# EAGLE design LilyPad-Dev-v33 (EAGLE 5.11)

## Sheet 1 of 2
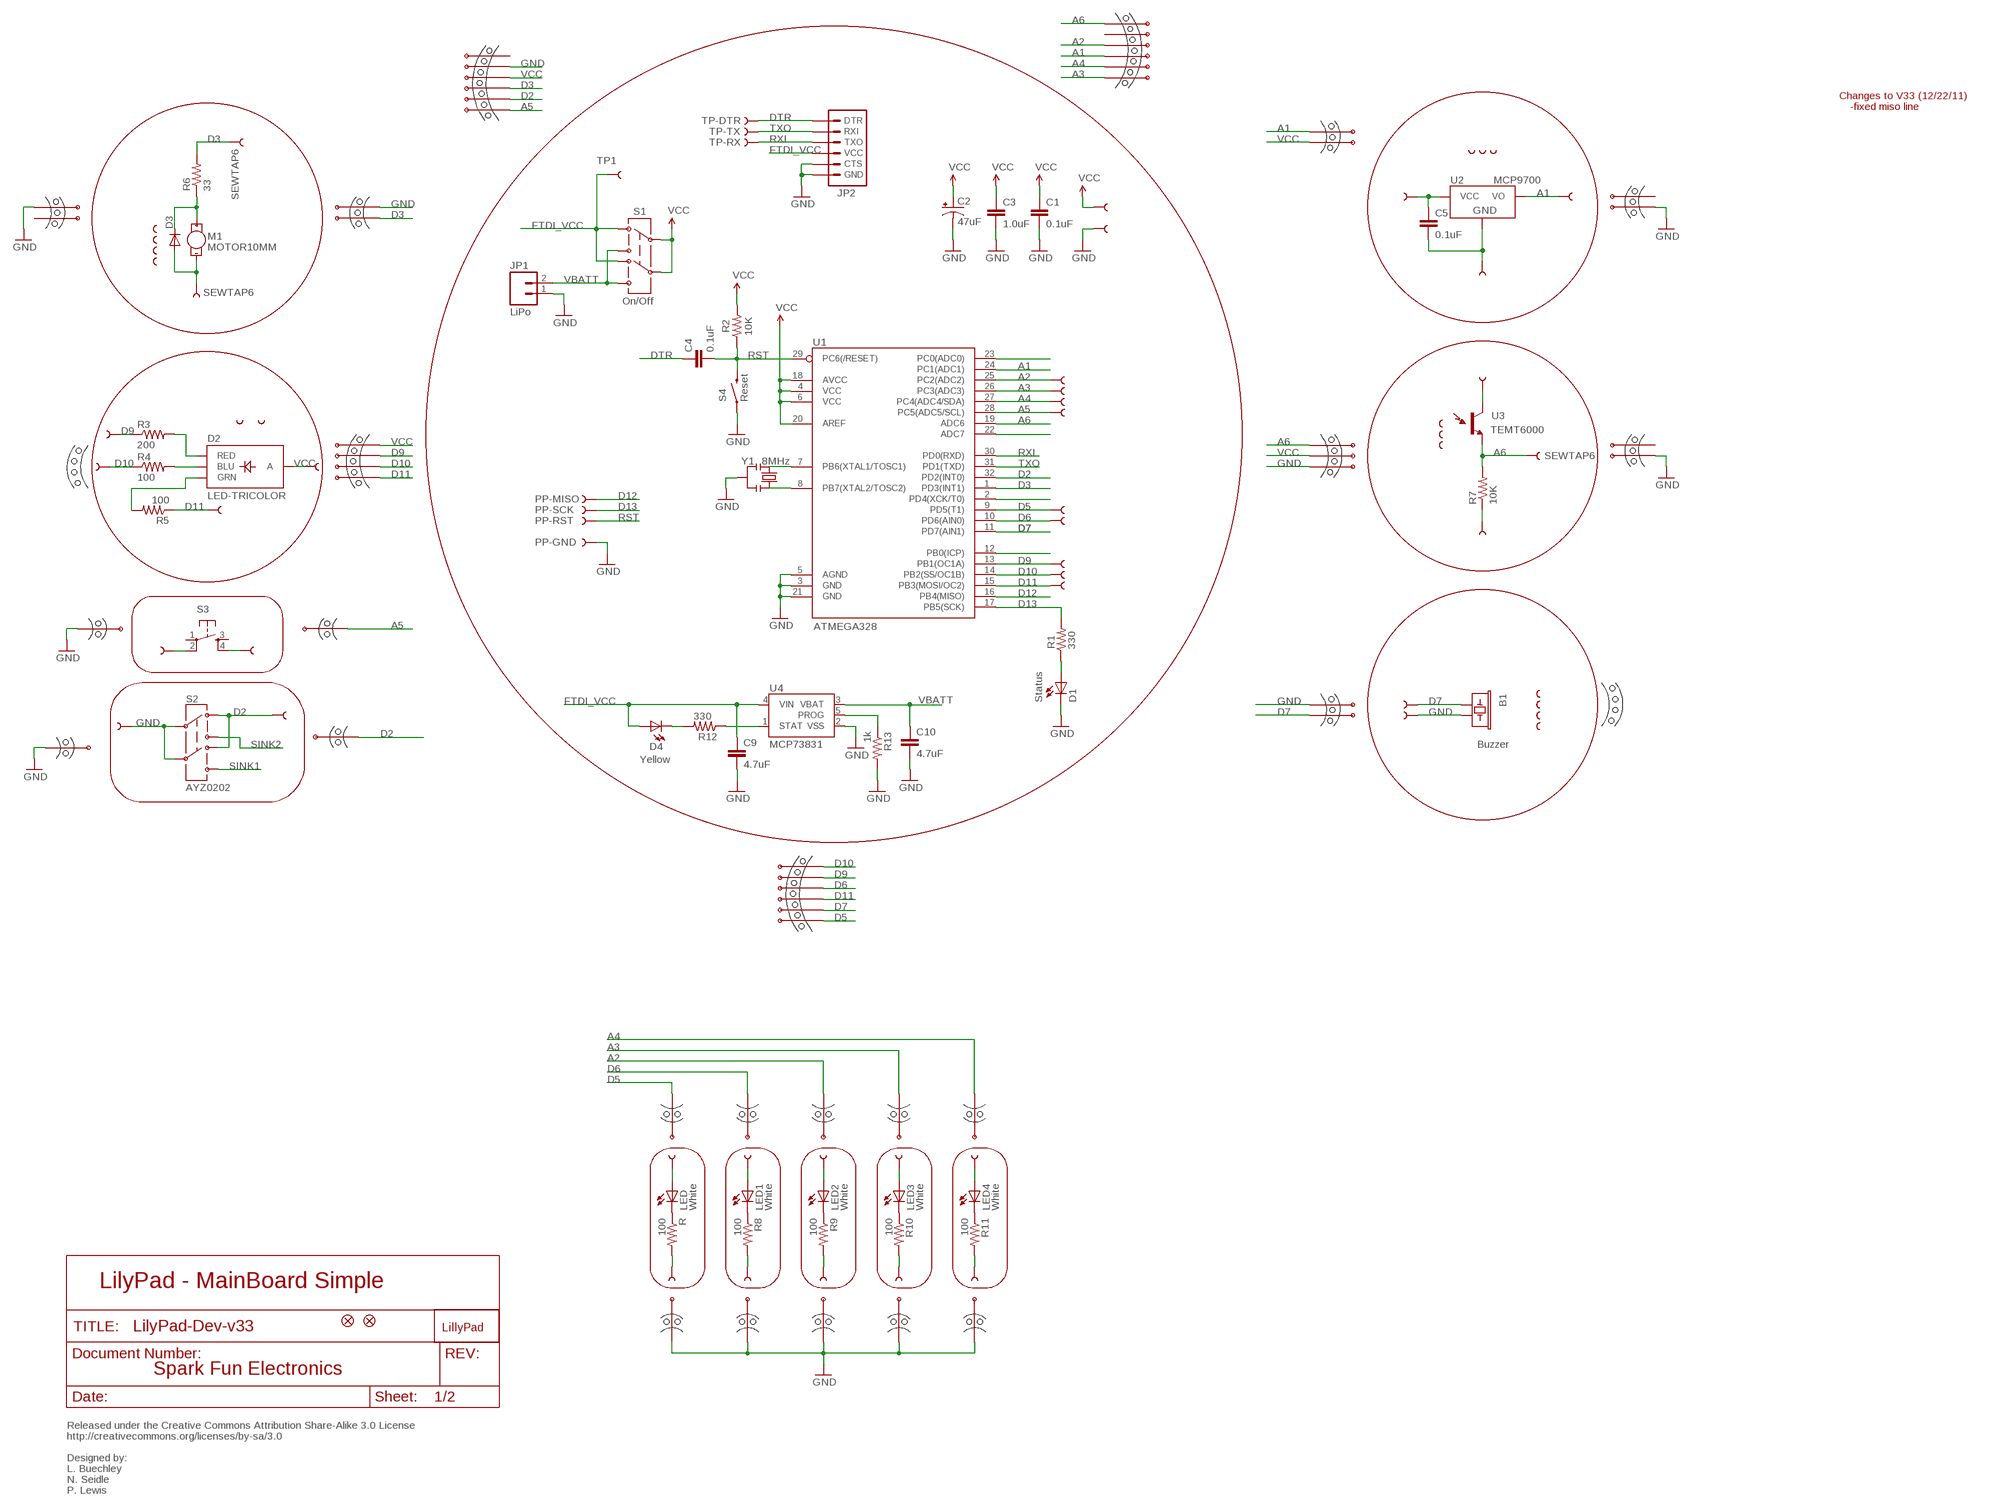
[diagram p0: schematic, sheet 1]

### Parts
1  SEWTAP-NOHOLE2  [PETAL-NOHOLE-2SIDE]
2  SEWTAP-NOHOLE2  [PETAL-NOHOLE-2SIDE]
3  SEWTAP-NOHOLE2  [PETAL-NOHOLE-2SIDE]
4  SEWTAP-NOHOLE2  [PETAL-NOHOLE-2SIDE]
A2/16  SEWTAP9  [PETAL-LONG-1-2SIDE]
A3/17  SEWTAP9  [PETAL-LONG-1-2SIDE]
A4/18  SEWTAP9  [PETAL-LONG-1-2SIDE]
A5/19  SEWTAP9  [PETAL-LONG-1-2SIDE]
B1  Buzzer  BUZZERSMD2  [BUZZER-CCV]
BUTTON-  SEWTAP8  SEWTAP4  [PETAL-SMALL]
BUTTONS  SEWTAP8  SEWTAP4  [PETAL-SMALL]
C1  0.1uF  CAP0402-CAP  [0402-CAP]
C2  47uF  CAP_POL3528  [EIA3528]
C3  1.0uF  CAP0402-CAP  [0402-CAP]
C4  0.1uF  CAP0402-CAP  [0402-CAP]
C5  0.1uF  CAP0603-CAP  [0603-CAP]
C9  4.7uF  CAP0402-CAP  [0402-CAP]
C10  4.7uF  CAP0402-CAP  [0402-CAP]
D1  Status  LED0603  [LED-0603]
D2  LED-TRICOLOR  [LED-TRICOLOR-SMD]
D3  DIODESOD  [SOD-323]
D4  Yellow  LED0603  [LED-0603]
JP1  LiPo  M02-JST-2MM-SMT  [JST-2-SMD]
JP2  ARDUINO_SERIAL_PROGRAMSMD  [1X06-SMD]
JP3  FIDUCIAL1X2  [FIDUCIAL-1X2]
JP4  FIDUCIAL1X2  [FIDUCIAL-1X2]
LED  White  LED1206  [LED-1206]
LED1  White  LED1206  [LED-1206]
LED2  White  LED1206  [LED-1206]
LED3  White  LED1206  [LED-1206]
LED4  White  LED1206  [LED-1206]
LED+  SEWTAP6  [PETAL-SMALL-2SIDE]
LED+1  SEWTAP6  [PETAL-SMALL-2SIDE]
LED+2  SEWTAP6  [PETAL-SMALL-2SIDE]
LED+3  SEWTAP6  [PETAL-SMALL-2SIDE]
LED+4  SEWTAP6  [PETAL-SMALL-2SIDE]
LED-  SEWTAP6  [PETAL-SMALL-2SIDE]
LED-1  SEWTAP6  [PETAL-SMALL-2SIDE]
LED-2  SEWTAP6  [PETAL-SMALL-2SIDE]
LED-3  SEWTAP6  [PETAL-SMALL-2SIDE]
LED-4  SEWTAP6  [PETAL-SMALL-2SIDE]
LIGHT1  SEWTAP-NOHOLE2  [PETAL-NOHOLE-2SIDE]
LIGHT2  SEWTAP-NOHOLE2  [PETAL-NOHOLE-2SIDE]
LIGHT3  SEWTAP-NOHOLE2  [PETAL-NOHOLE-2SIDE]
LIGHT+  SEWTAP6  SEWTAP4  [PETAL-SMALL]
LIGHT-  SEWTAP6  SEWTAP4  [PETAL-SMALL]
LIGHTS  SEWTAP6  SEWTAP4  [PETAL-SMALL]
LOGO  LOGO-LPLPA  [LOGO-LPA]
M1  MOTOR10MM  [VIBE-MOTOR-10MM]
PP-GND  TEST-POINT3X5  [PAD.03X.05]
PP-MISO  TEST-POINT3X5  [PAD.03X.05]
PP-RST  TEST-POINT3X5  [PAD.03X.05]
PP-SCK  TEST-POINT3X5  [PAD.03X.05]
R  100  RESISTOR0603-RES  [0603-RES]
R1  330  RESISTOR0402-RES  [0402-RES]
R2  10K  RESISTOR0402-RES  [0402-RES]
R3  200  RESISTOR0402-RES  [0402-RES]
R4  100  RESISTOR0402-RES  [0402-RES]
R5  100  RESISTOR0402-RES  [0402-RES]
R6  33  RESISTOR0402-RES  [0402-RES]
R7  10K  RESISTOR0402-RES  [0402-RES]
R8  100  RESISTOR0603-RES  [0603-RES]
R9  100  RESISTOR0603-RES  [0603-RES]
R10  100  RESISTOR0603-RES  [0603-RES]
R11  100  RESISTOR0603-RES  [0603-RES]
R12  330  RESISTOR0402-RES  [0402-RES]
R13  1k  RESISTOR0402-RES  [0402-RES]
S1  On/Off  AYZ0202  [AYZ0202]
S2  AYZ0202  [AYZ0202]
S3  TAC_SWITCHSMD  [TACTILE_SWITCH_SMD]
S4  Reset  SWITCH-MOMENTARY-2SMD  [TACTILE_SWITCH_SMD]
SLIDEOFF  SEWTAP8  SEWTAP4  [PETAL-SMALL]
SLIDEON  SEWTAP8  SEWTAP4  [PETAL-SMALL]
TEMP1  SEWTAP-NOHOLE2  [PETAL-NOHOLE-2SIDE]
TEMP2  SEWTAP-NOHOLE2  [PETAL-NOHOLE-2SIDE]
TEMP3  SEWTAP-NOHOLE2  [PETAL-NOHOLE-2SIDE]
TEMP+  SEWTAP6  SEWTAP4  [PETAL-SMALL]
TEMP-  SEWTAP6  SEWTAP4  [PETAL-SMALL]
TEMPS  SEWTAP6  SEWTAP4  [PETAL-SMALL]
TP1  TEST-POINT3X5  [PAD.03X.05]
TP-DTR  TEST-POINT3X5  [PAD.03X.05]
TP-RX  TEST-POINT3X5  [PAD.03X.05]
TP-TX  TEST-POINT3X5  [PAD.03X.05]
U1  ATMEGA328  ATMEGA168  [TQFP32-08]
U2  MCP9700  MCP9700SMD  [SOT23-3]
U3  TEMT6000  [TEMT6000-SEN]
U4  MCP73831  [SOT23-5]
U$1  SEWTAP9  [PETAL-LONG-1-2SIDE]
U$2  MOUSE-BITE-2  [MOUSE-BITE-2]
U$3  MOUSE-BITE-2  [MOUSE-BITE-2]
U$4  SEWTAP9  [PETAL-LONG-1-2SIDE]
U$5  MOUSE-BITE-2  [MOUSE-BITE-2]
U$6  MOUSE-BITE-2  [MOUSE-BITE-2]
U$7  MOUSE-BITE-66  [MOUSE-BITE-6]
U$8  MOUSE-BITE-66  [MOUSE-BITE-6]
U$10  MOUSE-BITE-12_HOLES  [MOUST-BITE-1-(2_HOLES)]
U$11  MOUSE-BITE-12_HOLES  [MOUST-BITE-1-(2_HOLES)]
U$12  MOUSE-BITE-12_HOLES  [MOUST-BITE-1-(2_HOLES)]
U$13  MOUSE-BITE-12_HOLES  [MOUST-BITE-1-(2_HOLES)]
U$14  MOUSE-BITE-12_HOLES  [MOUST-BITE-1-(2_HOLES)]
U$15  MOUSE-BITE-12_HOLES  [MOUST-BITE-1-(2_HOLES)]
U$16  MOUSE-BITE-12_HOLES  [MOUST-BITE-1-(2_HOLES)]
U$17  MOUSE-BITE-12_HOLES  [MOUST-BITE-1-(2_HOLES)]
U$18  MOUSE-BITE-12_HOLES  [MOUST-BITE-1-(2_HOLES)]
U$19  MOUSE-BITE-12_HOLES  [MOUST-BITE-1-(2_HOLES)]
U$20  MOUSE-BITE-4  [MOUSE-BITE-4]
U$22  SEWTAP6  [PETAL-SMALL-2SIDE]
U$23  SEWTAP6  [PETAL-SMALL-2SIDE]
U$24  SEWTAP6  [PETAL-SMALL-2SIDE]
U$25  SEWTAP6  [PETAL-SMALL-2SIDE]
U$26  SEWTAP-NOHOLE2  [PETAL-NOHOLE-2SIDE]
U$27  SEWTAP-NOHOLE2  [PETAL-NOHOLE-2SIDE]
U$32  MOUSE-BITE-2  [MOUSE-BITE-2]
U$32-  SEWTAP6  SEWTAP4  [PETAL-SMALL]
U$33  MOUSE-BITE-3  [MOUSE-BITE-3]
U$33+  SEWTAP6  SEWTAP4  [PETAL-SMALL]
U$37  SEWTAP9  [PETAL-LONG-1-2SIDE]
U$39  SEWTAP9  [PETAL-LONG-1-2SIDE]
U$40  MOUSE-BITE-1  [MOUSE-BITE-1]
U$41  SEWTAP9  [PETAL-LONG-1-2SIDE]
U$42  MOUSE-BITE-1  [MOUSE-BITE-1]
U$43  SEWTAP9  [PETAL-LONG-1-2SIDE]
U$44  MOUSE-BITE-1  [MOUSE-BITE-1]
U$45  SEWTAP9  [PETAL-LONG-1-2SIDE]
U$46  MOUSE-BITE-1  [MOUSE-BITE-1]
U$47  MOUSE-BITE-2  [MOUSE-BITE-2]
U$48  MOUSE-BITE-3(NO_PADS)  [MOUSE-BITE-3(NO_PADS)]
U$49  MOUSE-BITE-3(NO_PADS)  [MOUSE-BITE-3(NO_PADS)]
U$51  MOUSE-BITE-66  [MOUSE-BITE-6]
VIBE1  SEWTAP-NOHOLE2  [PETAL-NOHOLE-2SIDE]
VIBE2  SEWTAP-NOHOLE2  [PETAL-NOHOLE-2SIDE]
VIBE3  SEWTAP-NOHOLE2  [PETAL-NOHOLE-2SIDE]
VIBE4  SEWTAP-NOHOLE2  [PETAL-NOHOLE-2SIDE]
VIBE+  SEWTAP6  SEWTAP4  [PETAL-SMALL]
VIBE-  SEWTAP6  SEWTAP4  [PETAL-SMALL]
Y1  8MHz  RESONATORSMD  [RESONATOR-SMD]

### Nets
A1: TEMPS.1 U1.24(PC1(ADC1)) U2.2(VO) U$2.P$1 U$7.P$4
A2: A2/16.1 U1.25(PC2(ADC2)) U$7.P$3 U$12.P$1
A3: A3/17.1 U1.26(PC3(ADC3)) U$7.P$6 U$13.P$1
A4: A4/18.1 U1.27(PC4(ADC4/SDA)) U$7.P$5 U$14.P$1
A5: A5/19.1 BUTTONS.1 S3.2 U1.28(PC5(ADC5/SCL)) U$8.P$1 U$40.P$1
A6: LIGHTS.1 R7.2 U1.19(ADC6) U3.EMITTER(E1) U$7.P$1 U$33.P$1
BLU: D2.B(BLU) R4.2
D2: S2.3 S2.6 SLIDEON.1 U1.32(PD2(INT0)) U$8.P$2 U$46.P$1
D3: R6.2 U1.1(PD3(INT1)) U$5.P$1 U$8.P$3 VIBE+.1
D5: U1.9(PD5(T1)) U$10.P$1 U$41.1 U$51.P$1
D6: U1.10(PD6(AIN0)) U$1.1 U$11.P$1 U$51.P$4
D7: B1.+ U1.11(PD7(AIN1)) U$32.P$2 U$33+.1 U$51.P$2
D9: R3.1 U1.13(PB1(OC1A)) U$20.P$3 U$22.1 U$37.1 U$51.P$5
D10: R4.1 U1.14(PB2(SS/OC1B)) U$20.P$2 U$24.1 U$39.1 U$51.P$6
D11: R5.1 U1.15(PB3(MOSI/OC2)) U$4.1 U$20.P$1 U$23.1 U$51.P$3
D12: PP-MISO.P$1 U1.16(PB4(MISO))
D13: PP-SCK.P$1 R1.2 U1.17(PB5(SCK))
DTR: C4.1 JP2.1(DTR) TP-DTR.P$1
FTDI_VCC: C9.1 D4.A JP2.4(VCC) S1.3 S1.6 TP1.P$1 U4.4(VIN)
GND [VCC]: B1.- BUTTON-.1 C1.2 C2.C(-) C3.2 C5.2 C9.2 C10.2 D1.C D3.2(A) JP1.1 JP2.5(CTS) JP2.6(GND) LIGHT-.1 M1.- PP-GND.P$1 R7.1 R13.2 S2.2 S2.5 S3.4 S4.1 SLIDEOFF.1 TEMP-.1 U1.3(GND) U1.5(AGND) U1.21(GND) U2.3(GND) U4.2(VSS) U$3.P$1 U$5.P$2 U$6.P$1 U$8.P$5 U$15.P$1 U$16.P$1 U$17.P$1 U$18.P$1 U$19.P$1 U$32-.1 U$32.P$1 U$33.P$3 U$42.P$1 U$43.1 U$44.P$1 U$47.P$1 VIBE-.1 Y1.2
GRN: D2.G(GRN) R5.2
N$1: U1.7(PB6(XTAL1/TOSC1)) Y1.1
N$2: D1.A R1.1
N$3: U1.8(PB7(XTAL2/TOSC2)) Y1.3
N$5: U1.23(PC0(ADC0))
N$8: U1.22(ADC7)
N$10: D3.1(C) M1.+ R6.1
N$12: U1.2(PD4(XCK/T0))
N$14: U1.12(PB0(ICP))
N$18: LED.C R.1
N$19: LED+.1 LED.A
N$20: LED-.1 R.2
N$21: LED1.C R8.1
N$22: LED1.A LED+1.1
N$23: LED-1.1 R8.2
N$24: LED2.C R9.1
N$25: LED2.A LED+2.1
N$26: LED-2.1 R9.2
N$27: LED3.C R10.1
N$28: LED3.A LED+3.1
N$29: LED-3.1 R10.2
N$30: LED4.C R11.1
N$31: LED4.A LED+4.1
N$32: LED-4.1 R11.2
N$33: D4.C R12.2
PROG: R13.1 U4.5(PROG)
RED: D2.R(RED) R3.2
RST: C4.2 PP-RST.P$1 R2.1 S4.3 U1.29(PC6(/RESET))
RXI: JP2.3(TXO) TP-RX.P$1 U1.30(PD0(RXD))
SINK1: S2.4
SINK2: S2.1
STAT: R12.1 U4.1(STAT)
TXO: JP2.2(RXI) TP-TX.P$1 U1.31(PD1(TXD))
VBATT: C10.1 JP1.2 S1.1 S1.4 U4.3(VBAT)
VCC [VCC]: C1.1 C2.A(+) C3.1 C5.1 D2.A LIGHT+.1 R2.2 S1.2 S1.5 TEMP+.1 U1.4(VCC) U1.6(VCC) U1.18(AVCC) U1.20(AREF) U2.1(VCC) U3.COLLECTOR(C1) U$2.P$2 U$8.P$4 U$20.P$4 U$25.1 U$33.P$2 U$45.1
Unconnected: S3.1 S3.3 U$3.P$2 U$6.P$2 U$7.P$2 U$8.P$6 U$47.P$2

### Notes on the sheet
- Changes to V33 (12/22/11)
- -fixed miso line
- LilyPad - MainBoard Simple
- Spark Fun Electronics
- Released under the Creative Commons Attribution Share-Alike 3.0 License
- http://creativecommons.org/licenses/by-sa/3.0
- Designed by:
- L. Buechley
- N. Seidle
- P. Lewis

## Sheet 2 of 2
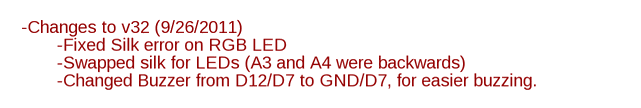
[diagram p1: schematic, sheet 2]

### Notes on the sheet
- -Changes to v32 (9/26/2011)
- -Fixed Silk error on RGB LED
- -Swapped silk for LEDs (A3 and A4 were backwards)
- -Changed Buzzer from D12/D7 to GND/D7, for easier buzzing.

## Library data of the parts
1-4 LIGHT1-LIGHT3 TEMP1-TEMP3 U$26 U$27 VIBE1-VIBE4 = LilyPad-Wearables:SEWTAP-NOHOLE
A2/16 A3/17 A4/18 A5/19 BUTTON- BUTTONS LED+ LED+1-LED+4 LED- LED-1-LED-4 LIGHT+ LIGHT- LIGHTS SLIDEOFF SLIDEON TEMP+ TEMP- TEMPS U$1 U$4 U$22-U$25 U$32- U$33+ U$37 U$39 U$41 U$43 U$45 VIBE+ VIBE- = LilyPad-Wearables:SEWTAP
B1 = SparkFun:BUZZER: Buzzer 12mm
C1 C3-C5 C9 C10 = SparkFun:CAP: Capacitor
C2 = SparkFun:CAP_POL: Capacitor Polarized
D1 D4 = SparkFun:LED: LEDs
D2 = SparkFun:LED-TRICOLOR: Tri-Color LED SMD Proven layout and schematic for triple color LED in SMD package - common anode. Spark Fun Electronics SKU : COM-07844
D3 = SparkFun:DIODE: Diode
JP1 = SparkFun:M02: Header 2
JP2 = SparkFun:ARDUINO_SERIAL_PROGRAM
JP3 JP4 = SparkFun:FIDUCIAL: Fiducial Alignment Points
LED LED1-LED4 = SparkFun-3-2-07:LED: LEDs
LOGO = LilyPad-Wearables:LOGO-LP
M1 = SparkFun:MOTOR: Vibration Motor
PP-GND PP-MISO PP-RST PP-SCK TP1 TP-DTR TP-RX TP-TX = SparkFun:TEST-POINT
R R1-R13 = SparkFun:RESISTOR: Resistor
S1 S2 = SparkFun:AYZ0202: SPDT Slide Switch Simple SMD single-pull double-throw slide switch. Good for less than 350mA power switch, switching UARTs between devices, etc. Spark Fun Electronics SKU : COM-00597
S3 = SparkFun:TAC_SWITCH: Momentary Switch Button commonly used for reset or general input. Spark Fun Electronics SKU : COM-00097
S4 = SparkFun:SWITCH-MOMENTARY-2
U1 = SparkFun:ATMEGA168
U2 = SparkFun:MCP9700
U3 = SparkFun:TEMT6000: Ambient Light Sensor
U4 = SparkFun:MCP73831: Microchip's MCP73831 Miniature single cell, fully integrated Li-Ion, Li-polymer charge management controller http://ww1.microchip.com/downloads/en/DeviceDoc/21984a.pdf
U$2 U$3 U$5 U$6 U$32 U$47 = Testing:MOUSE-BITE-2
U$7 U$8 U$51 = Testing:MOUSE-BITE-6
U$10-U$19 U$40 U$42 U$44 U$46 = Testing:MOUSE-BITE-1
U$20 = Testing:MOUSE-BITE-4
U$33 = Testing:MOUSE-BITE-3
U$48 U$49 = Testing:MOUSE-BITE-3(NO_PADS)
Y1 = SparkFun:RESONATOR: Resonator Small SMD resonator. This is the itty bitty 10/20MHz resonators with built in caps. CSTCE10M0G55 and CSTCE20M0V53. Footprint has been reviewed closely but hasn't been tested yet.

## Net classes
1 VCC: width 0.203 mm

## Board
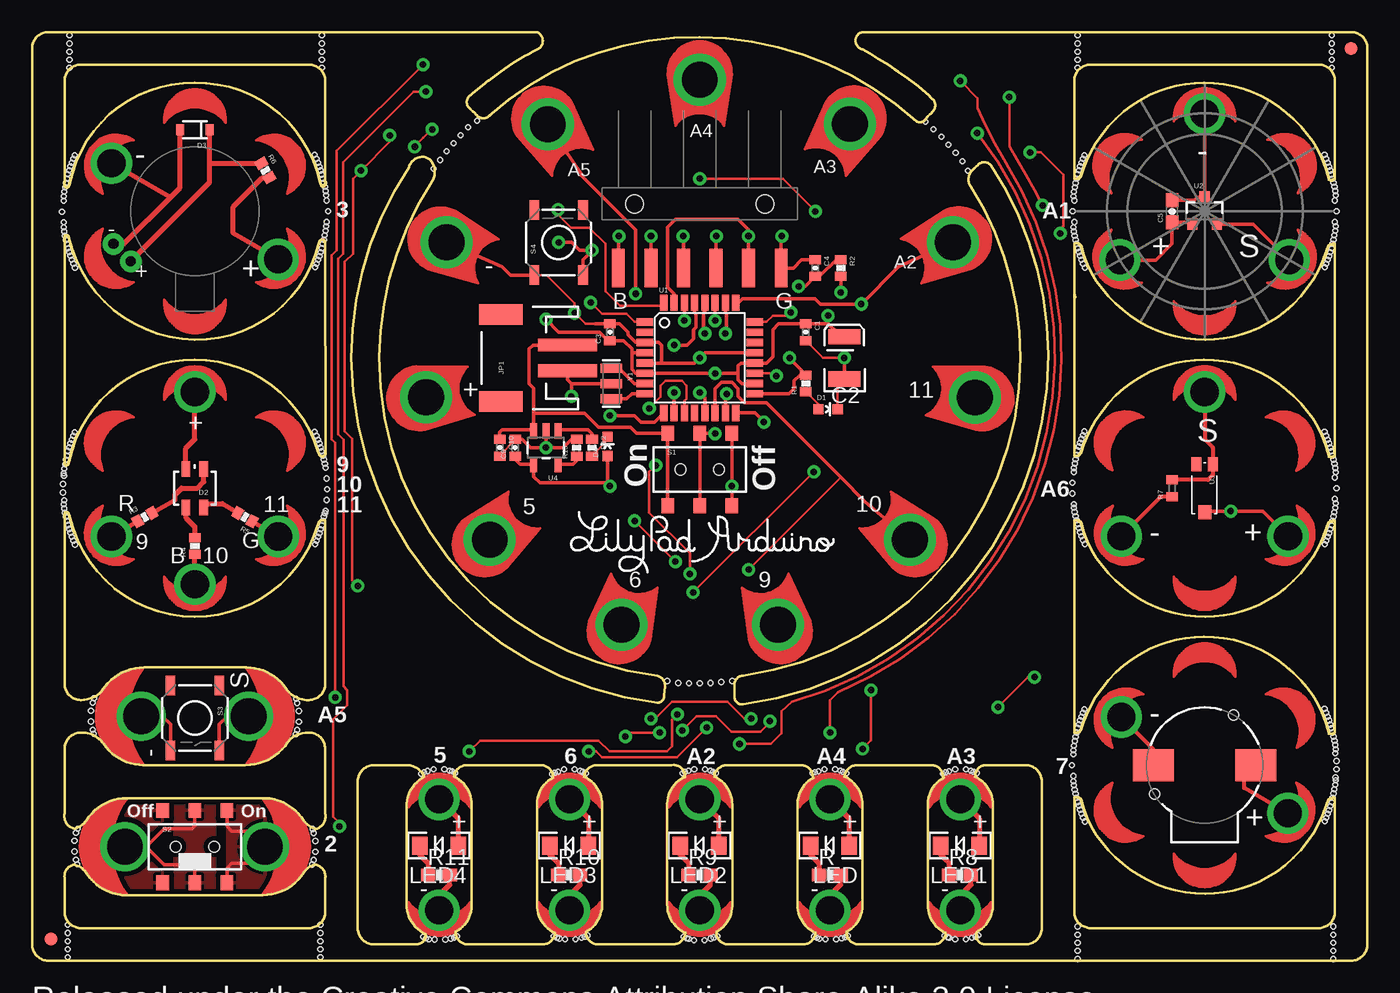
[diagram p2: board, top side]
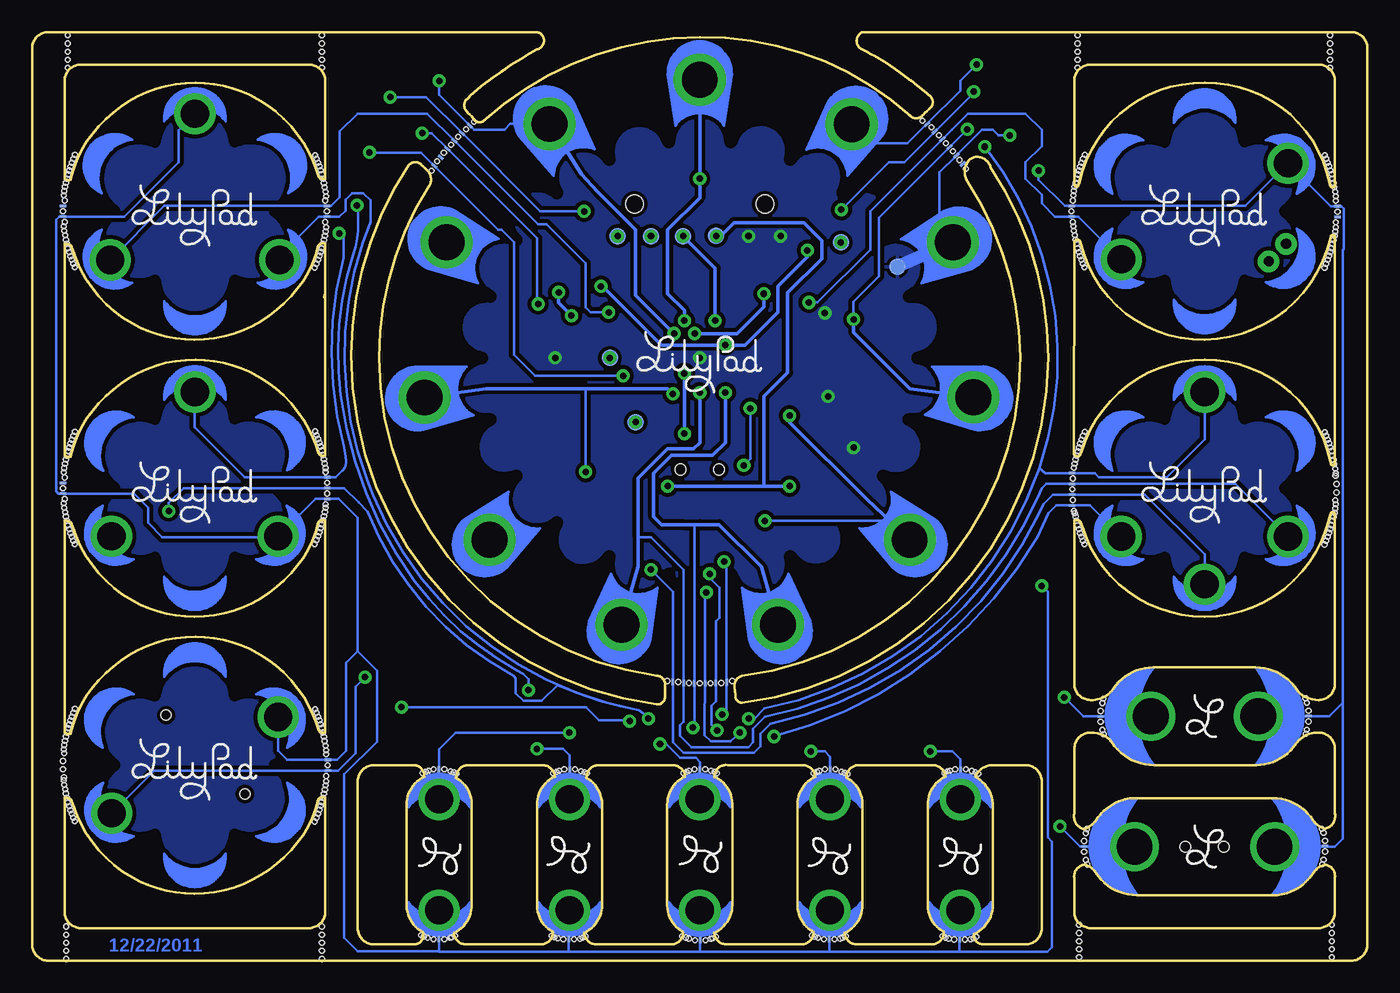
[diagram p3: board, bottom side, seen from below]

Size 104.14 x 72.39 mm. Coordinates in mm from the lower left corner, seen from the top.
Outline: 297 segments
Copper layers (1*16): Top 0.035mm / dielectric 1.5mm / Bottom 0.035mm
Design rules "SparkFun *": minimum track width 6mil, minimum drill 15mil, track to track 8mil, track to pad 8mil, pad to pad 8mil, via to via 8mil, smd to smd 8mil, copper to edge 10mil, drill to drill 8mil, minimum pad ring 12mil, minimum via ring 10mil, stop-mask expansion 4mil, vias tented up to drill 20mil, thermal gap 10mil
Holes 0.38 mm at 101.63,38.4 101.63,35.31 73.3,1.78 73.58,1.88 73.79,1.98 71.53,1.78 71.4,1.83 71.17,1.93 63.14,1.75 63.4,1.83 63.6,1.93 61.42,1.7 61.21,1.78 60.99,1.88 52.93,1.73 53.16,1.8 53.44,1.91 51.21,1.7 51.05,1.75 50.83,1.85 42.85,1.78 43.1,1.85 43.31,1.96 41.12,1.73 40.92,1.8 40.69,1.91 32.66,1.73 32.92,1.8 33.12,1.91 30.94,1.68 30.73,1.75 30.51,1.85 30.84,14.78 30.58,14.68 30.35,14.58 32.56,14.81 32.77,14.76 32.99,14.63 41.02,14.73 40.77,14.66 40.56,14.55 42.75,14.78 42.95,14.71 43.18,14.61 51.18,14.81 50.93,14.71 50.72,14.61 52.91,14.81 53.11,14.73 53.34,14.63 61.32,14.76 61.06,14.68 60.86,14.61 63.04,14.81 63.25,14.73 63.5,14.61 71.5,14.76 71.25,14.68 71.04,14.58 73.23,14.81 73.43,14.73 73.66,14.63 101.47,2.67 101.47,2.03 101.47,1.4 101.47,0.76 101.47,0.13 81.53,2.67 81.53,2.03 81.53,1.4 81.53,0.76 81.53,0.13 101.35,72.14 101.35,71.5 101.35,70.87 101.35,70.23 101.35,69.6 81.53,72.14 81.53,71.5 81.53,70.87 81.53,70.23 81.53,69.6 22.48,2.79 22.48,2.16 22.48,1.52 22.48,0.89 22.48,0.25 2.79,2.79 2.79,2.16 2.79,1.52 2.79,0.89 2.79,0.25 2.92,72.14 2.92,71.5 2.92,70.87 2.92,70.23 2.92,69.6 22.61,72.14 22.61,71.5 22.61,70.87 22.61,70.23 22.61,69.6 101.68,35.66 101.55,34.95 101.68,38.07 101.57,38.73 101.5,34.62 101.42,34.29 101.35,33.93 101.24,33.63 101.14,33.32 101.04,33.05 100.94,32.74 100.81,32.46 101.5,39.07 101.42,39.37 101.32,39.7 101.24,40.01 101.14,40.31 101.04,40.61 100.91,40.92 100.79,41.22 81.25,35.31 81.25,38.4 81.33,38.76 81.31,34.98 81.38,39.09 81.46,39.42 81.53,39.78 81.64,40.08 81.74,40.39 81.84,40.67 81.94,40.97 82.07,41.25 81.38,34.65 81.46,34.34 81.56,34.01 81.64,33.71 81.74,33.4 81.84,33.1 81.97,32.79 82.09,32.49 101.63,59.99 101.63,56.9 101.68,57.25 101.55,56.54 101.68,59.66 101.57,60.33 101.5,56.21 101.42,55.88 101.35,55.52 101.24,55.22 101.14,54.91 101.04,54.64 100.94,54.33 100.81,54.05 101.5,60.66 101.42,60.96 101.32,61.29 101.24,61.59 101.14,61.9 101.04,62.2 100.91,62.51 100.79,62.81 101.63,16.81 101.63,13.72 101.68,14.07 101.55,13.36 101.68,16.48 101.57,17.14 101.5,13.03 101.42,12.7 101.35,12.34 101.24,12.04 101.14,11.73 101.04,11.46 100.94,11.15 100.81,10.87 101.5,17.48 101.42,17.78 101.32,18.11 101.24,18.41 101.14,18.72 101.04,19.02 100.91,19.33 100.79,19.63 81.25,13.67 81.25,16.76 81.2,16.41 81.33,17.12 81.2,14 81.31,13.34 81.38,17.45 81.46,17.78 81.53,18.14 81.64,18.44 81.74,18.75 81.84,19.02 81.94,19.33 82.07,19.61 81.38,13 81.46,12.7 81.56,12.37 81.64,12.06 81.74,11.76 81.84,11.46 81.97,11.15 82.09,10.85 81.25,56.85 81.25,59.94 81.2,59.59 81.33,60.3 81.2,57.18 81.31,56.52 81.38,60.63 81.46,60.96 81.53,61.32 81.64,61.62 81.74,61.93 81.84,62.2 81.94,62.51 82.07,62.79 81.38,56.18 81.46,55.88 81.56,55.55 81.64,55.24 81.74,54.94 81.84,54.64 81.97,54.33 82.09,54.03 2.51,56.85 2.51,59.94 2.46,59.59 2.59,60.3 2.46,57.18 2.57,56.52 2.64,60.63 2.72,60.96 2.79,61.32 2.9,61.62 3,61.93 3.1,62.2 3.2,62.51 3.33,62.79 2.64,56.18 2.72,55.88 2.82,55.55 2.9,55.24 3,54.94 3.1,54.64 3.23,54.33 3.35,54.03 22.89,59.99 22.89,56.9 22.94,57.25 22.81,56.54 22.94,59.66 22.83,60.33 22.76,56.21 22.68,55.88 22.61,55.52 22.5,55.22 22.4,54.91 22.3,54.64 22.2,54.33 22.07,54.05 22.76,60.66 22.68,60.96 22.58,61.29 22.5,61.59 22.4,61.9 22.3,62.2 22.17,62.51 22.05,62.81 2.51,35.26 2.51,38.35 2.46,38 2.59,38.71 2.46,35.59 2.57,34.92 2.64,39.04 2.72,39.37 2.79,39.73 2.9,40.03 3,40.34 3.1,40.61 3.2,40.92 3.33,41.2 2.64,34.59 2.72,34.29 2.82,33.96 2.9,33.66 3,33.35 3.1,33.05 3.23,32.74 3.35,32.44 22.83,34.87 22.83,38.73 22.76,34.62 22.68,34.29 22.61,33.93 22.5,33.63 22.4,33.32 22.3,33.05 22.2,32.74 22.07,32.46 22.76,39.07 22.68,39.37 22.58,39.7 22.5,40.01 22.4,40.31 22.3,40.61 22.17,40.92 22.05,41.22 4.83,20.45 4.8,17.68 21.84,7.49 21.87,10.26 20.57,17.65 20.6,20.42 3.56,10.29 3.53,7.52
bRestrict: area 29.5,24.4 to 74.6,69.6; area 48.1,64.8 to 50.6,66; area 58.7,63.3 to 61.5,65; area 63.4,60.4 to 66,62.7; area 67.1,56.1 to 69.1,58.9; area 69.3,51.2 to 70.7,53.8; area 69.9,45.9 to 71.1,48.2; area 69.3,40.2 to 70.8,42.9; area 63.4,31.4 to 66.1,33.7; area 58.8,29 to 61.6,30.7; area 53.6,28 to 56,29.3; area 48.2,28 to 50.7,29.3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; 22 lines

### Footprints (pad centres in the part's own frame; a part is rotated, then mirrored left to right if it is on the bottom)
PETAL-LONG-1-2SIDE = drill 2.794 pad 4.064 round: 1 0.03,0
BUZZER-CCV = smd 3.2 x 2.5: + 4,0; - -4,0 | hole 0.8: -3.9,-2.25; 2.25,3.9
PETAL-MEDIUM-2SIDE = drill 2.794 round: 1 0,-0.254
0402-CAP = smd 0.7 x 0.9: 1 -0.65,0; 2 0.65,0
EIA3528 = smd 1.2 x 2.5: A 1.65,0; C -1.65,0
0603-CAP = smd 1.1 x 1: 1 -0.85,0; 2 0.85,0
LED-0603 = smd 0.8 x 0.8: A 0,-0.75; C 0,0.75
LED-TRICOLOR-SMD = smd 0.7 x 1.2: A 0.7,-1.5; B 0.7,1.5; G -0.7,1.5; R -0.7,-1.5
SOD-323 = smd 0.63 x 0.83: 1 -1.15,0; 2 1.15,0
JST-2-SMD = smd 1 x 4.6: 1 -1,-3.7; 2 1,-3.7 | smd 1.6 x 3.4: NC1 -3.4,1.5; NC2 3.4,1.5
1X06-SMD = smd 1 x 3: 1 -6.35,5; 2 -3.81,5; 3 -1.27,5; 4 1.27,5; 5 3.81,5; 6 6.35,5 | hole 1.4: -5.08,0; 5.08,0
FIDUCIAL-1X2 = smd 1 x 1: 1 0,0
LED-1206 = smd 1.2 x 1.4: A -1.5,0; C 1.5,0
PETAL-SMALL-2SIDE = drill 2.2 round: 1 0,0
VIBE-MOTOR-10MM = drill 0.8 pad 1.676 round: + -5,-3.9; - -6.35,-2.54
PAD.03X.05 = smd 1.27 x 1.27: P$1 0,0
0603-RES = smd 1.1 x 1: 1 -0.85,0; 2 0.85,0
0402-RES = smd 0.7 x 0.9: 1 -0.65,0; 2 0.65,0
C0402 = smd 0.7 x 0.9: 1 -0.65,0; 2 0.65,0
AYZ0202 = smd 1 x 1.15: 1 -2.5,2.825; 2 0,2.825; 3 2.5,2.825; 4 -2.5,-2.825; 5 0,-2.825; 6 2.5,-2.825 | hole 0.85: 1.5,0; -1.5,0
TACTILE_SWITCH_SMD = smd 1.524 x 0.762: 1 -2.54,1.905; 2 2.54,1.905; 3 -2.54,-1.905; 4 2.54,-1.905
TQFP32-08 = smd 1.27 x 0.559: 1 -4.293,2.8; 2 -4.293,2; 3 -4.293,1.2; 4 -4.293,0.4; 5 -4.293,-0.4; 6 -4.293,-1.2; 7 -4.293,-2; 8 -4.293,-2.8; 17 4.293,-2.8; 18 4.293,-2; 19 4.293,-1.2; 20 4.293,-0.4; 21 4.293,0.4; 22 4.293,1.2; 23 4.293,2; 24 4.293,2.8 | smd 0.559 x 1.27: 9 -2.8,-4.293; 10 -2,-4.293; 11 -1.2,-4.293; 12 -0.4,-4.293; 13 0.4,-4.293; 14 1.2,-4.293; 15 2,-4.293; 16 2.8,-4.293; 25 2.8,4.293; 26 2,4.293; 27 1.2,4.293; 28 0.4,4.293; 29 -0.4,4.293; 30 -1.2,4.293; 31 -2,4.293; 32 -2.8,4.293
SOT23-3 = smd 0.8 x 0.9: 1 -0.95,-1; 2 0.95,-1; 3 0,1.1
TEMT6000-SEN = smd 1.1 x 0.8: BASE -1.87,-0.65; EMITTER -1.87,0.65 | smd 1.1 x 1: COLLECTOR 1.86,0.01
SOT23-5 = smd 0.55 x 1.2: 1 -0.95,-1.3; 2 0,-1.3; 3 0.95,-1.3; 4 0.95,1.3; 5 -0.95,1.3
MOUSE-BITE-2 = smd 0.203 x 0.508 bottom: P$1 -0.419,0; P$2 0.419,0 | hole 0.381: -0.838,0.127; 0,0; 0.838,0.127
MOUSE-BITE-6 = smd 0.203 x 0.508 bottom: P$1 -2.095,0.089; P$2 -1.257,0.038; P$3 -0.419,0; P$4 0.419,0; P$5 1.257,0.038; P$6 2.095,0.114 | hole 0.381: -2.527,0.191; -1.676,0.025; -0.838,0; 0,0; 0.838,0.025; 1.676,0.102; 2.527,0.191
MOUST-BITE-1-(2_HOLES) = smd 0.203 x 0.508 bottom: P$1 -0.013,0 | hole 0.381: -0.432,0; 0.406,0
MOUSE-BITE-4 = smd 0.203 x 0.508 bottom: P$1 -1.257,0; P$2 -0.419,0; P$3 0.419,0; P$4 1.257,0 | hole 0.381: -1.676,0.127; -0.838,0.051; 0,0; 0.838,0.051; 1.676,0.127
MOUSE-BITE-3 = smd 0.203 x 0.508 bottom: P$1 -0.851,0; P$2 -0.013,0; P$3 0.826,0 | hole 0.381: -1.27,0.127; -0.432,0; 0.406,0; 1.245,0.127
MOUSE-BITE-1 = smd 0.203 x 0.508 bottom: P$1 -0.013,0 | hole 0.381: -0.432,0; 0.406,0; -1.067,0.127; 1.041,0.127
MOUSE-BITE-3(NO_PADS) = hole 0.381: -0.965,0.076; -0.33,0; 0.33,0; 0.94,0.102
RESONATOR-SMD = smd 0.7 x 1.7: 1 -1.2,0; 2 0,0; 3 1.2,0

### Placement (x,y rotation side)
1  91.44,22.74 180 top
2  97.94,18.99 120 top
3  91.44,7.74 0 top
4  84.94,11.49 300 top
A2/16  71.84,56.03 204.5 top
A3/17  63.81,65.25 237.3 top
A4/18  52.07,68.69 270 top
A5/19  40.2,65.23 302.7 top
B1  91.44,15.24 0 top
BUTTON-  SEWTAP8  [PETAL-MEDIUM-2SIDE]  8.76,19.05 270 top
BUTTONS  SEWTAP8  [PETAL-MEDIUM-2SIDE]  16.64,19.05 90 top
C1  60.34,48.99 270 top
C2  63.34,46.99 90 top
C3  45.07,48.99 90 top
C4  61.07,53.99 270 top
C5  88.9,58.42 90 top
C9  37.67,39.99 90 top
C10  36.47,39.99 270 top
D1  62.07,42.99 270 top
D2  12.7,36.83 180 top
D3  12.7,64.77 180 top
D4  44.87,40.09 0 top
JP1  38.07,46.99 90 top
JP2  52.07,58.99 180 top
JP3  102.87,71.12 0 top
JP4  1.47,1.68 0 top
LED  62.21,8.97 180 top
LED1  72.37,8.97 180 top
LED2  52.05,8.97 180 top
LED3  41.89,8.97 180 top
LED4  31.73,8.97 180 top
LED+  62.23,12.57 180 top
LED+1  72.39,12.57 180 top
LED+2  52.07,12.57 180 top
LED+3  41.91,12.57 180 top
LED+4  31.75,12.57 180 top
LED-  62.23,3.94 0 top
LED-1  72.39,3.94 0 top
LED-2  52.07,3.94 0 top
LED-3  41.91,3.94 0 top
LED-4  31.75,3.94 0 top
LIGHT1  84.94,40.59 240 top
LIGHT2  91.44,29.34 0 top
LIGHT3  97.93,40.58 120 top
LIGHT+  SEWTAP6  [PETAL-SMALL-2SIDE]  97.94,33.08 60 top
LIGHT-  SEWTAP6  [PETAL-SMALL-2SIDE]  84.95,33.08 300 top
LIGHTS  SEWTAP6  [PETAL-SMALL-2SIDE]  91.44,44.33 180 top
LOGO  52.07,32.99 0 top
LOGO1  LOGO-LPL  [LOGO-L]  12.7,8.89 0 bottom
LOGO2  LOGO-LPL  [LOGO-L]  12.7,19.05 0 bottom
LOGO3  LOGO-LPL  [LOGO-L]  62.31,8.26 90 bottom
LOGO4  LOGO-LPL  [LOGO-L]  72.34,8.15 90 bottom
LOGO5  LOGO-LPL  [LOGO-L]  51.99,8.31 90 bottom
LOGO6  LOGO-LPL  [LOGO-L]  41.94,8.15 90 bottom
LOGO7  LOGO-LPL  [LOGO-L]  31.72,8.15 90 bottom
M1  12.7,58.42 0 top
PP-GND  36.67,54.09 0 bottom
PP-MISO  57.07,41.99 0 bottom
PP-RST  41.07,55.99 0 bottom
PP-SCK  59.07,46.99 0 bottom
R  62.21,6.68 0 top
R1  60.34,44.99 90 top
R2  63.07,53.99 270 top
R3  8.8,34.58 30 top
R4  12.7,32.33 90 top
R5  16.6,34.58 150 top
R6  18.2,61.6 300 top
R7  10K  [C0402]  88.9,36.83 90 top
R8  72.37,6.68 0 top
R9  52.05,6.68 0 top
R10  41.89,6.68 0 top
R11  31.73,6.68 0 top
R12  43.67,39.99 270 top
R13  42.47,39.99 90 top
S1  52.07,38.29 0 top
S2  12.7,8.89 0 top
S3  12.7,18.92 270 top
S4  41.07,55.99 90 top
SLIDEOFF  SEWTAP8  [PETAL-MEDIUM-2SIDE]  7.49,8.89 270 top
SLIDEON  SEWTAP8  [PETAL-MEDIUM-2SIDE]  17.91,8.89 90 top
TEMP1  84.84,62.22 240 top
TEMP2  91.44,50.82 0 top
TEMP3  98.04,62.22 120 top
TEMP+  SEWTAP6  [PETAL-SMALL-2SIDE]  84.84,54.62 300 top
TEMP-  SEWTAP6  [PETAL-SMALL-2SIDE]  91.44,66.02 180 top
TEMPS  SEWTAP6  [PETAL-SMALL-2SIDE]  98.04,54.62 60 top
TP1  50.8,56.52 0 bottom
TP-DTR  58.47,56.49 0 bottom
TP-RX  53.37,56.49 0 bottom
TP-TX  55.87,56.49 90 bottom
U1  52.07,46.99 0 top
U2  91.44,58.42 0 top
U3  91.44,36.83 270 top
U4  40.07,39.99 180 top
U$1  45.96,26.16 73.7 top
U$2  81.15,58.42 270 top
U$3  101.73,58.42 90 top
U$4  73.55,43.9 171.8 top
U$5  23.09,58.42 90 top
U$6  101.73,36.83 90 top
U$7  71.47,63.6 131 top
U$8  32.87,63.73 228 top
U$9  [LOGO-LILYPAD]  12.7,36.83 0 bottom
U$10  31.75,14.91 0 top
U$11  41.88,14.91 180 top
U$12  52.04,14.91 180 top
U$13  72.39,14.91 180 top
U$14  62.2,14.91 180 top
U$15  31.83,1.65 0 top
U$16  41.99,1.68 0 top
U$17  52.04,1.6 0 top
U$18  72.42,1.68 0 top
U$19  62.31,1.68 0 top
U$20  23.01,36.75 90 top
U$21  LOGO-LPLP  [LOGO-LILYPAD]  52.07,46.99 0 bottom
U$22  6.2,33.07 300 top
U$23  19.2,33.07 60 top
U$24  12.7,29.34 0 top
U$25  12.7,44.32 180 top
U$26  19.2,40.59 120 top
U$27  6.2,40.59 240 top
U$28  [LILYPAD-BRD-LAYERS-SMALL]  91.44,58.42 0 top
U$29  LOGO-LPLP  [LOGO-LILYPAD]  12.7,58.42 0 bottom
U$30  LOGO-LPLP  [LOGO-LILYPAD]  91.44,58.42 0 bottom
U$31  LOGO-LPLP  [LOGO-LILYPAD]  91.44,36.83 0 bottom
U$32  81.08,15.24 270 top
U$32-  SEWTAP6  [PETAL-SMALL-2SIDE]  84.94,18.99 240 top
U$33  81.13,36.83 270 top
U$33+  SEWTAP6  [PETAL-SMALL-2SIDE]  97.93,11.49 60 top
U$34  [LILYPAD-BRD-LAYERS-SMALL]  91.44,36.83 0 top
U$35  LOGO-LPLP  [LOGO-LILYPAD]  91.44,15.24 0 bottom
U$36  [LILYPAD-BRD-LAYERS-SMALL]  91.44,15.24 0 top
U$37  58.18,26.16 106.3 top
U$38  [LILYPAD-BRD-LAYERS-SMALL]  12.7,36.83 0 top
U$39  68.47,32.78 139.1 top
U$40  20.8,19.05 90 top
U$41  35.67,32.78 40.9 top
U$42  4.6,19.05 270 top
U$43  32.3,56.02 335.5 top
U$44  3.3,8.92 270 top
U$45  30.69,43.91 8.2 top
U$46  22.1,8.92 90 top
U$47  2.34,58.39 270 top
U$48  2.41,36.83 270 top
U$49  101.73,15.24 90 top
U$50  [LILYPAD-BRD-LAYERS-SMALL]  12.7,58.42 0 top
U$51  52.07,21.62 0 top
VIBE1  6.2,54.67 300 top
VIBE2  12.7,50.92 0 top
VIBE3  19.2,62.17 120 top
VIBE4  12.7,65.92 180 top
VIBE+  SEWTAP6  [PETAL-SMALL-2SIDE]  19.2,54.67 60 top
VIBE-  SEWTAP6  [PETAL-SMALL-2SIDE]  6.2,62.17 240 top
Y1  45.17,44.99 270 top

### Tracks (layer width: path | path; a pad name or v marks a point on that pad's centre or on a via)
A1  (via drill 0.51)
  Top 0.203: U1.24 57.28,49.79 57.78,50.29 58.93,50.29 v59.18,50.55
  Top 0.254: 92.44,57.42 95.24,57.42 TEMPS.1
  Top 0.406: 92.44,57.42 U2.2
  Bottom 0.203: v59.18,50.55 60.58,50.55 60.96,50.93 60.96,54.36 64.01,57.4 64.68,57.4 U$7.P$4 73.32,66.04 78.74,66.04 80.14,64.64 80.14,59.51 80.81,58.84 U$2.P$1 93.82,58.84 TEMPS.1
A2  (via drill 0.51)
  Top 0.203: v73.71,64.52 arc-113 59.26,20.19 58.45,19.46 58.45,17.73 57.61,16.89 v55.17,16.89
  Top 0.254: A2/16.1 67.57,54.09 v64.67,51.19 61.48,51.19 61.06,51.61 55.38,51.61 54.96,51.19 U1.25
  Bottom 0.203: v64.67,51.19 64.77,51.29 64.77,56.33 U$7.P$3 72.98,64.52 v73.71,64.52 | 52.06,14.44 U$12.P$1 52.06,15.48 52.38,15.8 53.62,15.8 54.71,16.89 v55.17,16.89
A3  (via drill 0.51)
  Top 0.203: v72.39,68.58 73.74,67.23 73.74,66.5 arc10 75.79,62.46 arc-100 62.87,20.93 62.23,20.3 v62.23,17.78
  Top 0.254: U1.26 54.07,50.49 54.17,50.39 54.17,48.99 v54.07,48.89
  Bottom 0.203: A3/17.1 66.86,65.22 67.31,64.77 69.67,64.77 U$7.P$6 72.39,67.49 v72.39,68.58 | U$13.P$1 72.4,16.5 71.12,17.78 v62.23,17.78
  Bottom 0.254: A3/17.1 61.27,61.29 60.07,59.99 57.07,56.99 57.07,51.89 v54.07,48.89
A4  (via drill 0.51)
  Top 0.203: v61.09,58.42 58.55,60.96 v52.07,60.96 | v76.2,67.31 76.2,63.5 76.81,62.46 arc-3 v78.79,58.88 | v65.43,21.08 65.43,17.17 v64.77,16.51
  Top 0.254: v53.27,49.89 U1.27
  Bottom 0.203: v61.09,58.42 64.51,58.42 U$7.P$5 73.4,67.31 v76.2,67.31 | v65.43,21.08 65.43,21.95 65.86,22.38 66.37,22.66 arc25 74.3,29.59 arc29 80.06,44.07 arc25 79.1,55.02 arc-26 v78.79,58.88 | v64.77,16.51 62.71,16.51 62.22,16.02 U$14.P$1
  Bottom 0.254: v53.27,49.89 53.27,50.69 54.57,51.99 54.57,56.99 52.07,59.49 v52.07,60.96 A4/18.1
A5  (via drill 0.51)
  Top 0.203: v30.48,69.85 23.75,63.12 23.75,55.37 23.37,54.99 23.37,40.64 23.65,40.36 v23.65,20.52
  Top 0.254: A5/19.1 42.87,61.29 42.87,61.19 47.07,56.99 v47.07,51.99 | U1.28 52.47,50.59 52.37,50.49 52.37,48.99 v52.47,48.89 | S3.2 14.61,18.41 15.24,19.05 BUTTONS.1
  Bottom 0.203: 16.89,19.04 BUTTONS.1 16.9,19.04 U$40.P$1 22.16,19.04 v23.65,20.52 | A5/19.1 38.72,63.7 35.86,63.7 U$8.P$1 31.75,67.81 31.75,68.58 v30.48,69.85
  Bottom 0.254: v47.07,51.99 47.07,50.99 49.17,48.89 v52.47,48.89
A6  (via drill 0.51)
  Top 0.203: U1.19 57.84,45.79 v58.04,45.59 | v80.19,56.69 80.44,57.3 80.44,61.27 78.69,63.02 v77.83,63.02
  Top 0.305: LIGHTS.1 91.44,40.64 92.08,40.01 92.08,38.69 | 92.08,38.69 92.08,38.61 | 92.08,38.69 U3.EMITTER 92.09,37.86 91.71,37.48 R7.2
  Bottom 0.203: v58.04,45.59 64.9,45.59 66.55,47.24 66.55,56.01 67.54,57 67.81,57 U$7.P$1 73.78,62.97 77.78,62.97 v77.83,63.02 | U$33.P$1 81.19,37.68 | U$33.P$1 80.45,37.68 79.96,38.18 arc-64 79.7,39.27 79.81,40.01 arc29 79.86,54.79 79.86,56.36 v80.19,56.69 | U$33.P$1 87.55,37.68 91.44,41.57 LIGHTS.1
BLU
  Top 0.406: D2.B 12,34.53 12.7,33.83 R4.2 12.75,32.93
D2  (via drill 0.51)
  Top 0.203: U1.32 49.04,51.05 45.85,51.05 44.7,52.2 44.7,55.88 43.43,57.15 42.04,57.15 41.02,58.17 v41.02,58.55 | v30.71,67.74 29.77,67.74 24.26,62.23 24.26,55.12 23.88,54.74 23.88,41.02 24.28,40.62 24.28,21.39 24.59,21.08 24.59,19.91 23.5,18.82 23.5,11.23 23.98,10.74 v23.98,10.46
  Top 0.254: S2.3 15.2,10.46 15.57,10.09 16.98,10.09 16.98,10.07 SLIDEON.1 16.86,7.59 15.57,7.59 15.2,7.22 S2.6
  Bottom 0.203: SLIDEON.1 22.09,8.89 U$46.P$1 22.42,8.9 v23.98,10.46 | v41.02,58.55 37.31,62.26 36.12,62.26 U$8.P$2 30.71,67.67 v30.71,67.74
  pour Top (isolate 0.381): 15.24,5.08 17.4,5.08 18.03,6.22 18.41,7.37 18.67,8.26 18.67,9.78 18.29,10.92 17.65,12.06 17.27,12.7 15.24,12.7
D3  (via drill 0.51)
  Top 0.203: U1.1 46.98,49.79 46.35,50.42 44.45,50.42 v43.56,51.31
  Top 0.406: VIBE+.1 15.7,56.72 15.7,58.77 17.95,61.02 18.55,61.02 18.53,61.04 R6.2
  Bottom 0.203: VIBE+.1 22.53,58 U$5.P$1 | U$5.P$1 23.02,58 23.11,57.91 | U$8.P$3 38.76,58.43 38.76,55.42 42.88,51.31 v43.56,51.31 | U$8.P$3 32.42,64.77 | U$5.P$1 24.37,58 25.4,59.03 25.4,59.69 26.67,60.96 26.67,62.23 25.4,63.5 25.4,64.77 26.67,66.04 31.15,66.04 U$8.P$3
D5  (via drill 0.51)
  Top 0.203: v50.16,31.11 v46.99,34.29 | v50.32,19.2 49.91,18.8 49.91,16.71 49.51,16.31 45.03,16.31 44.2,17.14 34.92,17.14 v34.09,16.31
  Top 0.254: U1.9 48.56,41.99 47.47,41.99 46.97,42.49 v45.07,42.49
  Bottom 0.203: v46.99,34.29 37.18,34.29 U$41.1 | v50.16,31.11 49.97,30.92 U$51.P$1 49.97,19.55 v50.32,19.2 | 31.74,14.63 U$10.P$1 31.74,15.68 32.36,16.31 v34.09,16.31
  Bottom 0.254: U$41.1 39.07,35.99 45.07,41.99 v45.07,42.49
D6  (via drill 0.51)
  Top 0.203: v52.6,18.16 50.29,15.85 44.45,15.85 43.99,16.31 v43.41,16.31
  Top 0.254: v50.07,44.29 U1.10
  Bottom 0.203: 52.07,33.99 51.65,33.99 | 53.34,33.99 52.49,33.99 U$51.P$4 52.49,18.27 v52.6,18.16 | 41.9,14.79 U$11.P$1 41.91,14.92 41.91,15.9 42.32,16.31 v43.41,16.31
  Bottom 0.254: v50.07,44.29 50.07,40.39 51.07,39.39 54.27,39.39 55.67,37.99 55.67,34.59 55.07,33.99 53.34,33.99 52.07,33.99 50.57,33.99 47.27,30.69 U$1.1
D7  (via drill 0.51)
  Top 0.203: U1.11 50.87,43.63 51.05,43.81 51.05,44.83 50.67,45.21 49.4,45.21 49.02,44.83 49.02,43.94 v48.13,43.05 | v48.64,38.61 48.13,38.1 48.13,34.92 51.31,31.75 v51.31,30.15 | v78.18,22.1 77.67,22.1 v75.34,19.76 | v57.53,18.67 57.53,18.57 56.79,17.83 54.56,17.83 53.34,19.05 51.82,19.05 v50.72,17.96
  Top 0.305: U$33+.1 94.53,13.46 94.53,15.24 95.55,15.35 B1.+
  Bottom 0.203: U$33+.1 94.6,14.82 U$32.P$2 80.28,14.82 78.92,16.18 78.92,21.36 v78.18,22.1 | v48.13,43.05 48.13,39.12 v48.64,38.61 | v51.31,30.15 51.31,29.84 50.52,29.06 50.52,26.75 50.81,26.45 U$51.P$2 50.81,20.23 51.16,19.89 51.16,18.39 v50.72,17.96 | v75.34,19.76 60.94,19.76 59.92,18.75 57.61,18.75 v57.53,18.67
D9  (via drill 0.51)
  Top 0.254: U1.13 52.47,43.89 v52.07,44.29
  Top 0.406: U$22.1 6.15,33.08 R3.1
  Bottom 0.203: U$22.1 10.3,37.17 U$20.P$3 25.06,37.17 25.4,36.83 25.7,36.14 arc54 46.97,19 47.9,18.06 47.9,17.02 48.28,16.64 52.7,16.64 53.62,17.55 53.62,18.34 53.34,18.62 53.34,20.32 U$51.P$5 53.33,30.47 55.88,33.02 56.87,33.02
  Bottom 0.254: v52.07,44.29 52.07,40.39 52.57,39.89 54.57,39.89 56.87,37.59 56.87,33.02 56.87,30.69 U$37.1
D10  (via drill 0.51)
  Top 0.203: v55.88,30.48 63.08,37.68
  Top 0.254: U$39.1 64.97,35.79 63.08,37.68 57.27,43.49 55.57,43.49 55.07,43.99 55.07,44.59 54.57,45.09 53.77,45.09 53.27,44.59 U1.14
  Top 0.406: 12.7,29.28 U$24.1 R4.1
  Bottom 0.203: U$24.1 R4.1 17.36,36.34 U$20.P$2 24.52,36.34 25.27,35.59 25.6,34.9 arc52 46.56,18.47 47.35,17.68 47.35,16.71 47.85,16.2 53.34,16.2 54.17,17.03 U$51.P$6 54.17,28.77 v55.88,30.48
D11  (via drill 0.51)
  Top 0.203: v51.56,28.7 v60.96,38.1 | v46.28,17.48 46.58,17.78 v48.95,17.78
  Top 0.254: U1.15 54.07,44.09 v54.17,44.19
  Top 0.406: U$23.1 R5.1
  Bottom 0.203: U$4.1 73.52,45.86 | v60.96,38.1 60.96,44.59 | U$23.1 21.63,35.5 U$20.P$1 24.24,35.5 24.87,34.87 25.76,33.02 arc45 v46.28,17.48 | U$51.P$3 51.64,21.6 | v51.56,28.7 51.65,28.61 U$51.P$3 | U$51.P$3 51.69,18.47 51.69,17.58 51.21,17.09 49.66,17.09 v48.95,17.78
  Bottom 0.254: v54.17,44.19 54.57,44.59 60.96,44.59 68.72,44.59 68.73,44.6 U$4.1
D12  (via drill 0.51)
  Top 0.254: U1.16 56.36,42.7 PP-MISO.P$1
  other vias: 57.07,41.99
D13  (via drill 0.51)
  Top 0.254: PP-SCK.P$1 R1.2 59.87,45.64 59.42,45.19 59.42,44.59 59.02,44.19 U1.17
  other vias: 59.07,46.99
DTR  (via drill 0.51)
  Top 0.254: TP-DTR.P$1 58.42,56.44 JP2.1 59.37,53.99 60.02,54.64 C4.1
  other vias: 58.47,56.49
FTDI_VCC  (via drill 0.51)
  Top 0.254: S1.3 v54.57,36.99 S1.6 | C9.1 37.67,39.09 38.07,38.69 U4.4 39.12,37.74 39.62,37.24 44.82,37.24 v45.07,36.99 44.87,37.19 D4.A | JP2.4 50.8,56.46 v50.77,56.49
  Bottom 0.254: v45.07,36.99 47.07,36.99 | 47.07,36.99 v54.57,36.99 | 47.07,36.99 47.07,43.99 45.21,45.85 45.21,52.07 42.55,54.74 42.55,56.13 43.94,57.53 49.4,57.53 50.44,56.49 v50.77,56.49 TP1.P$1
GND  (via drill 0.51)
  Top 0.203: C10.2 C9.2 | S4.1 40.11,53.45 42.31,51.25 v42.31,50.49 43.16,49.64 43.92,49.64 | C2.C 62.82,44.82 D1.C | v63.34,46.99 61.69,46.99 C1.2 | v27.89,64.34 27.89,63.83 v25.65,61.59 25.02,60.96 25.02,55.12 24.38,54.48 24.38,41.27 24.97,40.69 24.97,29.64 v25.4,29.21
  Top 0.254: U1.21 52.47,47.39 v52.07,46.99 51.67,46.59 49.07,46.59 | 49.07,46.59 U1.5 | 49.07,46.59 49.07,47.99 48.87,48.19 U1.3 47.07,48.19 46.47,48.79 46.47,48.99 45.82,49.64 C3.2 43.92,49.64 | U$43.1 PP-GND.P$1 37.31,53.45 S4.1 | v40.07,39.99 U4.2 | C2.C v63.34,46.99 | v40.07,39.99 41.42,39.99 42.07,40.64 R13.2 | C9.2 38.22,40.64 38.87,39.99 v40.07,39.99 | 42.07,44.99 Y1.2 | JP1.1 41.77,45.29 42.07,44.99 | v42.07,43.99 42.07,44.99 | JP2.6 45.72,56.44 v45.77,56.49 | JP2.5 v48.26,56.48 v48.27,56.49 | TEMP-.1 U2.3 90.89,59.52 90.64,59.27 C5.2 | S3.4 10.79,18.41 10.16,19.05 BUTTON-.1 | S2.2 12.7,10.52 12.47,10.29 10.29,10.29 8.89,8.89 | S2.5 12.7,7.36 12.57,7.49 10.29,7.49 8.89,8.89 | SLIDEOFF.1 8.89,8.89
  Top 0.305: R7.1 88.9,36.2 88.06,36.2 LIGHT-.1 | U$32-.1 87.44,16.49 B1.-
  Top 0.406: M1.- 7.16,55.88 10.8,59.52 | D3.2 11.55,60.27 10.8,59.52 | 10.8,59.52 10.75,59.57 VIBE-.1
  Bottom 0.203: U$43.1 33.38,57.06 33.38,61.45 U$8.P$5 | BUTTON-.1 U$42.P$1 2.98,19.06 1.93,20.12 | 7.2,8.93 SLIDEOFF.1 3.34,8.89 U$44.P$1 3.26,8.89 2.54,8.89 1.93,9.5 1.93,20.12 | U$8.P$5 | 78.74,24.13 78.74,34.52 80.24,36.02 81.11,36.02 U$33.P$3 82.03,36.01 LIGHT-.1 85.01,33.02 93.98,33.02 95.1,34.14 95.1,35.32 96.19,36.41 U$6.P$1 102.09,36.41 102.26,36.58 102.26,57.76 102.02,58 U$3.P$1 96.94,58 92.71,62.23 92.71,64.75 TEMP-.1 | 78.74,24.13 77.22,22.61 77.22,17.08 79.78,14.51 79.78,1.77 78.75,0.73 72.45,0.73 72.4,0.68 | v25.65,61.59 25.65,60.88 23.61,58.84 U$5.P$2 9.53,58.84 VIBE-.1 2.84,58.81 U$47.P$1 2.04,58.81 1.83,58.6 1.83,55.5 1.93,55.4 1.93,20.12 | U$8.P$5 30.05,64.77 29.21,64.77 28.78,64.34 v27.89,64.34 | 72.4,0.68 U$18.P$1 | 31.75,0.68 24.97,0.68 24.61,1.05 24.61,9.29 24.94,9.62 24.94,28.75 v25.4,29.21 | 31.75,0.68 41.91,0.68 | 41.91,0.68 52.07,0.68 | 52.07,0.68 62.23,0.68 | 62.23,0.68 72.4,0.68 | U$15.P$1 31.81,0.75 31.75,0.68 | U$16.P$1 41.97,0.75 41.91,0.68 | U$17.P$1 52.03,0.72 52.07,0.68 | U$19.P$1 62.29,0.75 62.23,0.68 | U$32-.1 84.94,16.36 84.24,15.66 U$32.P$1 80.35,15.66 79.63,16.38 79.63,23.24 78.74,24.13
  Bottom 1: U$43.1 PP-GND.P$1
  pour Bottom (isolate 0.305): 52.07,22 arc-90 27.08,46.99 27.08,47.02 arc-90 52.04,71.98 52.07,71.98 arc-90 77.06,46.99 77.06,46.96 arc-90 52.1,22
  pour Top (isolate 0.381): 14.22,5.08 14.22,12.7 11.18,12.7 11.18,5.08
GRN
  Top 0.406: R5.2 14.85,35.63 13.35,35.63 13.35,35.33 D2.G
N$1
  Top 0.254: U1.7 46.97,44.99 45.77,46.19 Y1.1
N$2
  Top 0.203: R1.1 61.32,43.36 D1.A
N$3
  Top 0.254: U1.8 46.77,44.19 46.37,43.79 Y1.3
N$4
  pour Bottom (isolate 0.305): 101.47,58.39 101.47,58.52 arc90 91.52,68.48 91.26,68.48 arc90 81.48,58.7 81.48,58.39 arc90 91.52,48.36 arc90
N$7
  pour Bottom (isolate 0.305): 101.47,36.8 101.47,36.93 arc90 91.52,46.89 91.26,46.89 arc90 81.48,37.11 81.48,36.8 arc90 91.52,26.77 arc90
N$9
  pour Bottom (isolate 0.305): 101.47,15.21 101.47,15.34 arc90 91.52,25.3 91.26,25.3 arc90 81.48,15.52 81.48,15.21 arc90 91.52,5.18 arc90
N$10
  Top 0.406: R6.1 17.86,62.16 17.85,62.17 13.85,62.17 | 13.85,62.17 D3.1 | M1.+ 13.85,60.67 13.85,62.17
N$11
  pour Bottom (isolate 0.305): 22.73,58.39 22.73,58.52 arc90 12.78,68.48 12.52,68.48 arc90 2.74,58.7 2.74,58.39 arc90 12.78,48.36 arc90
N$13
  pour Bottom (isolate 0.305): 22.73,36.8 22.73,36.93 arc90 12.78,46.89 12.52,46.89 arc90 2.74,37.11 2.74,36.8 arc90 12.78,26.77 arc90
N$18
  Top 0.254: 61.15,7.81 61.21,7.75
  Top 0.406: LED.C 60.71,8.25 61.15,7.81 61.36,7.6 R.1
N$19
  Top 0.406: 62.23,12.7 LED+.1 63.71,11.09 LED.A
N$20
  Top 0.406: LED-.1 62.23,5.08 63.06,5.91 R.2
N$21
  Top 0.254: 71.31,7.81 71.37,7.75
  Top 0.406: LED1.C 70.87,8.25 71.31,7.81 71.52,7.6 R8.1
N$22
  Top 0.406: 72.39,12.7 LED+1.1 73.87,11.09 LED1.A
N$23
  Top 0.406: LED-1.1 72.39,5.08 73.22,5.91 R8.2
N$24
  Top 0.254: 50.99,7.81 51.05,7.75
  Top 0.406: LED2.C 50.55,8.25 50.99,7.81 51.2,7.6 R9.1
N$25
  Top 0.406: 52.07,12.7 LED+2.1 53.55,11.09 LED2.A
N$26
  Top 0.406: LED-2.1 52.07,5.08 52.9,5.91 R9.2
N$27
  Top 0.254: 40.83,7.81 40.89,7.75
  Top 0.406: LED3.C 40.39,8.25 40.83,7.81 41.04,7.6 R10.1
N$28
  Top 0.406: 41.91,12.7 LED+3.1 43.39,11.09 LED3.A
N$29
  Top 0.406: LED-3.1 41.91,5.08 42.74,5.91 R10.2
N$30
  Top 0.254: 30.67,7.81 30.73,7.75
  Top 0.406: LED4.C 30.23,8.25 30.67,7.81 30.88,7.6 R11.1
N$31
  Top 0.406: 31.75,12.7 LED+4.1 33.23,11.09 LED4.A
N$32
  Top 0.406: LED-4.1 31.75,5.08 32.58,5.91 R11.2
N$33
  Top 0.203: R12.2 44.57,40.29 44.87,40.59 D4.C
PROG
  Top 0.254: 41.42,38.69 U4.5 42.17,38.69 42.47,38.99 R13.1
RED
  Top 0.406: R3.2 11.15,35.93 11.15,36.33 11.65,36.83 12.9,36.83 13.4,37.33 D2.R
RST  (via drill 0.51)
  Top 0.254: R2.1 62.72,54.64 61.42,53.34 C4.2 60.3,52.57 v59.77,52.57 | U1.29 51.67,50.49 51.77,50.39 51.77,49.39 51.57,49.19 51.57,48.49 51.07,47.99 v50.07,47.99 | PP-RST.P$1 42.07,55.99 42.69,55.37 v43.69,55.37 42.98,54.66 S4.3
  Bottom 0.254: v43.69,55.37 43.69,54.86 45.97,52.58 45.97,50.55 48.53,47.99 v50.07,47.99 55.07,47.99 59.17,52.09 59.65,52.57 v59.77,52.57
  other vias: 41.07,55.99
RXI  (via drill 0.51)
  Top 0.254: v50.87,49.89 U1.30 | JP2.3 53.34,56.46 TP-RX.P$1
  Bottom 0.254: v50.87,49.89 50.87,53.99 TP-RX.P$1
  other vias: 53.37,56.49
SINK1
  pour Top (isolate 0.381): 10.16,5.08 10.16,8.89 7.62,8.89 arc-223 6.73,8.38 6.73,8 7.06,6.86 7.54,5.84 8.13,5.08
SINK2
  pour Top (isolate 0.381): 10.16,10.16 10.16,12.7 8,12.7 7.37,11.56 6.86,10.29 6.73,9.65 8.76,9.14
STAT
  Top 0.254: R12.1 43.67,41.09 43.37,41.39 41.12,41.39 U4.1
TXO  (via drill 0.51)
  Top 0.254: U1.31 50.07,51.99 49.57,52.49 49.57,57.19 50.17,57.79 55.07,57.79 55.87,56.99 TP-TX.P$1 JP2.2
  other vias: 55.87,56.49
VBATT
  Top 0.254: S1.4 S1.1 47.15,41.12 46.67,41.59 44.17,41.59 43.07,42.69 39.12,42.69 | JP1.2 39.07,47.99 38.77,47.69 38.77,44.99 39.12,44.64 39.12,42.69 | C10.1 36.47,41.19 36.67,41.39 39.02,41.39 U4.3 39.12,42.69
VCC  (via drill 0.51)
  Top 0.203: v48.26,18.87 48.59,18.87 49.91,20.19 54.23,20.19 55.55,18.87 v56.08,18.87 | v29.84,63.45 arc-14 v31.2,64.8
  Top 0.254: 46.77,47.49 46.77,46.09 47.07,45.79 U1.6 v53.27,45.79 55.07,45.79 | 46.77,47.49 46.77,47.69 46.12,48.34 C3.1 44.92,48.34 44.27,48.99 41.07,48.99 v40.07,49.99 | U1.4 46.87,47.39 46.77,47.49 | S1.5 S1.2 53.24,41.12 v53.27,41.09 | 62.07,49.59 C2.A | 62.07,49.59 v62.07,50.29 | 62.07,49.59 62.02,49.64 C1.1 58.22,49.64 57.77,49.19 57.77,47.09 57.27,46.59 U1.20 55.27,46.59 55.07,46.39 55.07,45.79 | v63.07,52.09 R2.2 | U1.18 55.37,44.99 55.07,45.29 55.07,45.79 | TEMP+.1 87.64,54.62 88.9,55.88 C5.1 90.34,57.57 U2.1 | 91.53,35.05 v93.47,35.05 95.97,35.05 LIGHT+.1
  Top 0.305: 91.53,35.05 U3.COLLECTOR
  Top 0.406: D2.A 12,39.94 12.7,40.64 U$25.1 12.7,44.45 | U2.1 90.44,57.42
  Bottom 0.203: v40.07,49.99 40.07,51.37 38.1,53.34 38.1,57.9 U$8.P$4 v31.2,64.8 | U$20.P$4 22.77,38.01 | U$33.P$2 92.33,36.84 93.47,35.7 v93.47,35.05 | U$33.P$2 81.11,36.83 | 56.82,19.53 arc57 77.55,36.3 77.83,36.99 78,37.49 arc39 78.36,55.93 77.75,57.61 77.75,59.28 78.31,59.84 79.2,59.84 79.7,59.33 79.7,58.47 80.17,58 U$2.P$2 81.78,58 84.84,54.94 TEMP+.1 | 56.82,19.53 56.08,18.97 v56.08,18.87 | 25.58,38.41 arc60 47.02,19.66 47.8,18.87 v48.26,18.87 | 25.58,38.41 arc-57 v29.84,63.45 | U$20.P$4 25.13,38.01 25.58,38.41 | U$33.P$2 79.79,36.84 78.69,35.74 77.98,35 arc-40 66.6,22.2 66.42,22.02 66.42,20.85 65.81,20.24 64.39,20.24 63.14,21.49 62.36,21.16 arc-13 56.82,19.53 | U$20.P$4 21.27,38.01 20.95,37.69 15.65,37.69 12.7,40.64 U$25.1
  Bottom 0.254: v53.27,45.79 v53.27,41.09 | v63.07,52.09 63.07,51.29 v62.07,50.29 | v40.07,49.99 40.07,48.99 35.67,44.59 U$45.1

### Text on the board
Bottom: 12/22/2011
tPlace: A4 | - | - | A5 | A3 | 3 | A1 | + | + | S | A2 | - | B | G | + | 11 | + | S | 9 | On | Off | 10 | A6 | R | 11 | 11 | 5 | 10 | - | + | 9 | G | B | 10 | 6 | 9 | S | A5 | - | - | 5 | 6 | A2 | A4 | A3 | 7 | + | + | + | + | + | Off | On | + | 2 | - | - | - | - | - | Released under the Creative Commons Attribution Share-Alike 3.0 License | http://creativecommons.org/licenses/by-sa/3.0 | L. Buechley | N. Seidle | P. Lewis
